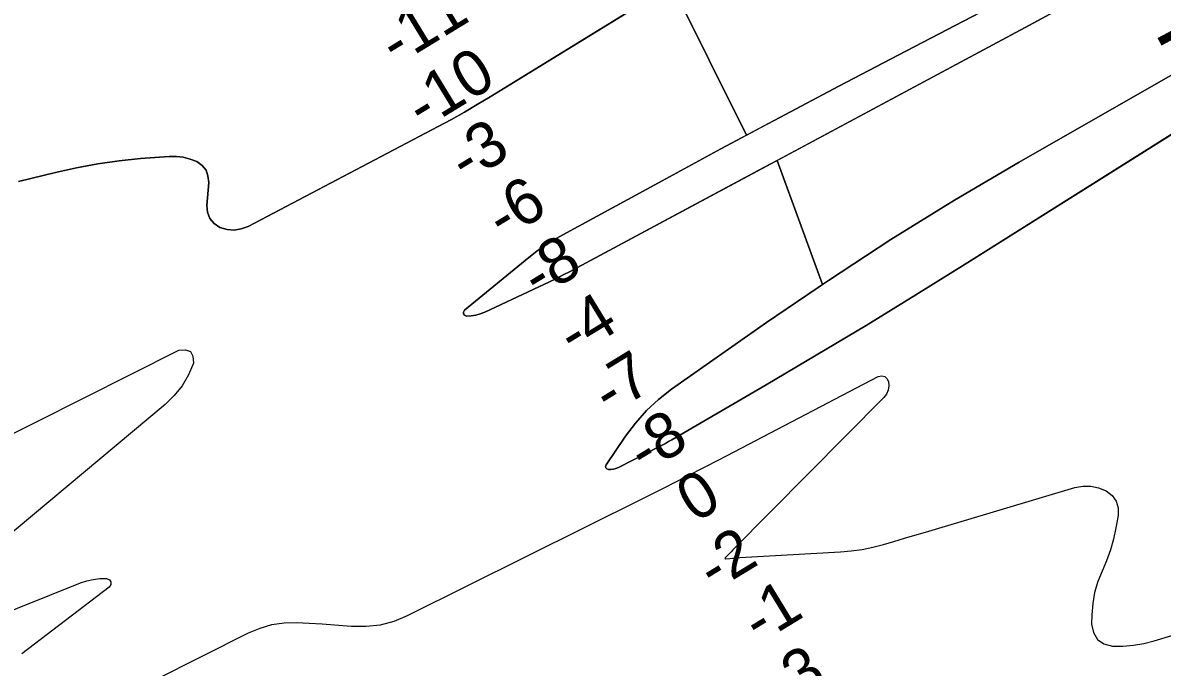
# Model space of a CAD drawing. Extents: x 3177385 to 3215275, y 903885 to 929304.
# Drawn here: x 3187679 to 3189350, y 911280 to 912224 of the extents above; entities that cross this region are included whole.
import ezdxf

# ---------------------------------------------------------------- set-up
doc = ezdxf.new("R2010")
doc.units = 0
for name, color, linetype in [('V-RIVR-RANG', 7, 'Continuous'), ('V-TOPO-DPTH', 7, 'Continuous'), ('V-TOPO-GNAM-IDEN', 7, 'Continuous'), ('V-TOPO-MINR', 7, 'Continuous')]:
    doc.layers.add(name, color=color, linetype=linetype)

msp = doc.modelspace()

# ---------------------------------------------------------------- linework, layer by layer
at = {"layer": 'V-TOPO-DPTH'}
for points in [[(3189564.8, 912490), (3189572.5, 912493.8), (3189580.2, 912497.4), (3189689.2, 912548.4), (3189695.8, 912550.8), (3189702.6, 912552.6), (3189709.6, 912553.3), (3189716.8, 912553.2), (3189719.6, 912551.5), (3189721.2, 912549.4), (3189720.7, 912546.9), (3189719, 912544.1), (3189600.1, 912467.4), (3189591.1, 912461.7), (3189582, 912456.2), (3189572.8, 912450.7), (3189563.5, 912445.4), (3189438.2, 912375.2), (3189366.1, 912335.1), (3189293.8, 912295.3), (3189221.3, 912255.9), (3189148.7, 912216.7), (3188785.3, 912022.1)], [(3189549.5, 912482.3), (3188962.3, 912176.5), (3188875.6, 912131), (3188789, 912085.2), (3188702.6, 912039), (3188616.4, 911992.5), (3188470.7, 911913.4), (3188457.7, 911905.8), (3188445.1, 911897.8), (3188432.8, 911889.1), (3188420.9, 911880), (3188326.6, 911803), (3188325.2, 911800), (3188325, 911797.4), (3188326.8, 911795.5), (3188329.8, 911794.1), (3188336.6, 911794.5), (3188343.4, 911795.5), (3188349.9, 911797.4), (3188356.4, 911799.9), (3188451.3, 911844.6), (3188461.4, 911849.4), (3188471.4, 911854.4), (3188481.4, 911859.5), (3188491.3, 911864.7), (3189148.7, 912216.7), (3189221.3, 912255.9)], [(3188651.4, 912291.8), (3188630.9, 912279.2), (3188740.2, 912059.2), (3188762.3, 912070.9), (3188789, 912085.2), (3188875.6, 912131), (3188962.3, 912176.5), (3189549.5, 912482.3), (3189557.1, 912486.2), (3189564.8, 912490)], [(3188942.4, 912470.6), (3188364.1, 912115.2), (3188345.4, 912103.9), (3188326.5, 912092.9), (3188307.4, 912082.3), (3188288.2, 912072), (3188009.6, 911925.5), (3187999.3, 911921.8), (3187988.9, 911920), (3187978.5, 911921.1), (3187968, 911924.1), (3187959.6, 911930), (3187953.2, 911937.2), (3187950, 911946.2), (3187948.8, 911956.4), (3187951.7, 911990.1), (3187950.6, 911999.6), (3187947.7, 912008), (3187941.9, 912014.9), (3187934.2, 912020.6), (3187924.4, 912024.3), (3187914.4, 912027), (3187904.2, 912028.1), (3187893.7, 912028.1), (3187851.7, 912024.8), (3187820.2, 912021.5), (3187788.9, 912017.2), (3187757.8, 912011.4), (3187726.8, 912004.6), (3187673, 911991.4)], [(3188785.3, 912022.1), (3188851.8, 911840.7), (3188860.3, 911846.5), (3188952, 911906.5), (3189045.3, 911963.9), (3189139.7, 912019.7), (3189637.3, 912304.4), (3189645.8, 912309.1), (3189654.4, 912313.8), (3189663.2, 912318.2), (3189671.9, 912322.5), (3189804.6, 912385.7), (3189813.9, 912389.4), (3189823.3, 912392.1), (3189833, 912393.6), (3189843, 912394.1), (3189847, 912392), (3189849.4, 912389.3), (3189849, 912385.8), (3189846.9, 912381.8), (3189714.5, 912284.4), (3189698, 912272.5), (3189681.2, 912260.9)], [(3189637.3, 912304.4), (3189139.7, 912019.7), (3189045.3, 911963.9), (3188952, 911906.5), (3188860.3, 911846.5), (3188769.7, 911784.8), (3188630.3, 911687), (3188611.2, 911672), (3188593.3, 911655.7), (3188577.3, 911637.5), (3188562.6, 911618.2), (3188534.2, 911576.2), (3188533.6, 911573.8), (3188533.9, 911571.8), (3188535.3, 911570.4), (3188537.6, 911569.3), (3188541.4, 911569.4), (3188545.2, 911569.9), (3188548.8, 911571), (3188552.3, 911572.4), (3188611.5, 911602.5), (3188616.4, 911605), (3188621.2, 911607.6), (3188626, 911610.3), (3188630.8, 911613), (3188768.8, 911693.4), (3188842.3, 911736.7), (3188915.5, 911780.5), (3188988.2, 911825.1), (3189060.7, 911870.1), (3189647.1, 912238.5)], [(3188740.2, 912059.2), (3188630.9, 912279.2), (3188364.1, 912115.2), (3188345.4, 912103.9), (3188326.5, 912092.9), (3188307.4, 912082.3), (3188288.2, 912072), (3188009.6, 911925.5), (3187999.3, 911921.8), (3187988.9, 911920), (3187978.5, 911921.1), (3187968, 911924.1), (3187959.6, 911930), (3187953.2, 911937.2), (3187950, 911946.2), (3187948.8, 911956.4), (3187951.7, 911990.1), (3187950.6, 911999.6), (3187947.7, 912008), (3187941.9, 912014.9), (3187934.2, 912020.6), (3187924.4, 912024.3), (3187914.4, 912027), (3187904.2, 912028.1), (3187893.7, 912028.1), (3187851.7, 912024.8), (3187820.2, 912021.5), (3187788.9, 912017.2), (3187757.8, 912011.4), (3187726.8, 912004.6), (3187673, 911991.4)], [(3189480.2, 912133.7), (3189060.7, 911870.1), (3188988.2, 911825.1), (3188915.5, 911780.5), (3188842.3, 911736.7), (3188768.8, 911693.4), (3188630.8, 911613), (3188626, 911610.3), (3188621.2, 911607.6), (3188616.4, 911605), (3188611.5, 911602.5), (3188552.3, 911572.4), (3188548.8, 911571), (3188545.2, 911569.9), (3188541.4, 911569.4), (3188537.6, 911569.3), (3188535.3, 911570.4), (3188533.9, 911571.8), (3188533.6, 911573.8), (3188534.2, 911576.2), (3188562.6, 911618.2), (3188577.3, 911637.5), (3188593.3, 911655.7), (3188611.2, 911672), (3188630.3, 911687), (3188769.7, 911784.8), (3188840.7, 911833.1)], [(3188840.7, 911833.1), (3188851.8, 911840.7), (3188785.3, 912022.1), (3188765.8, 912011.7), (3188491.3, 911864.7), (3188481.4, 911859.5), (3188471.4, 911854.4), (3188461.4, 911849.4), (3188451.3, 911844.6), (3188356.4, 911799.9), (3188349.9, 911797.4), (3188343.4, 911795.5), (3188336.6, 911794.5), (3188329.8, 911794.1), (3188326.8, 911795.5), (3188325, 911797.4), (3188325.2, 911800), (3188326.6, 911803), (3188420.9, 911880), (3188432.8, 911889.1), (3188445.1, 911897.8), (3188457.7, 911905.8), (3188470.7, 911913.4), (3188616.4, 911992.5), (3188702.6, 912039), (3188740.2, 912059.2)]]:
    msp.add_lwpolyline(points, dxfattribs=at)
at = {"layer": 'V-TOPO-MINR'}
for points in [[(3189549.5, 912482.3), (3188962.3, 912176.5), (3188875.6, 912131), (3188789, 912085.2), (3188702.6, 912039), (3188616.4, 911992.5), (3188470.7, 911913.4), (3188457.7, 911905.8), (3188445.1, 911897.8), (3188432.8, 911889.1), (3188420.9, 911880), (3188326.6, 911803), (3188325.2, 911800), (3188325, 911797.4), (3188326.8, 911795.5), (3188329.8, 911794.1), (3188336.6, 911794.5), (3188343.4, 911795.5), (3188349.9, 911797.4), (3188356.4, 911799.9), (3188451.3, 911844.6), (3188461.4, 911849.4), (3188471.4, 911854.4), (3188481.4, 911859.5), (3188491.3, 911864.7), (3189148.7, 912216.7), (3189221.3, 912255.9)], [(3187673, 911991.4), (3187726.8, 912004.6), (3187757.8, 912011.4), (3187788.9, 912017.2), (3187820.2, 912021.5), (3187851.7, 912024.8), (3187893.7, 912028.1), (3187904.2, 912028.1), (3187914.4, 912027), (3187924.4, 912024.3), (3187934.2, 912020.6), (3187941.9, 912014.9), (3187947.7, 912008), (3187950.6, 911999.6), (3187951.7, 911990.1), (3187948.8, 911956.4), (3187950, 911946.2), (3187953.2, 911937.2), (3187959.6, 911930), (3187968, 911924.1), (3187978.5, 911921.1), (3187988.9, 911920), (3187999.3, 911921.8), (3188009.6, 911925.5), (3188288.2, 912072), (3188307.4, 912082.3), (3188326.5, 912092.9), (3188345.4, 912103.9), (3188364.1, 912115.2), (3188942.4, 912470.6)], [(3189637.3, 912304.4), (3189139.7, 912019.7), (3189045.3, 911963.9), (3188952, 911906.5), (3188860.3, 911846.5), (3188769.7, 911784.8), (3188630.3, 911687), (3188611.2, 911672), (3188593.3, 911655.7), (3188577.3, 911637.5), (3188562.6, 911618.2), (3188534.2, 911576.2), (3188533.6, 911573.8), (3188533.9, 911571.8), (3188535.3, 911570.4), (3188537.6, 911569.3), (3188541.4, 911569.4), (3188545.2, 911569.9), (3188548.8, 911571), (3188552.3, 911572.4), (3188611.5, 911602.5), (3188616.4, 911605), (3188621.2, 911607.6), (3188626, 911610.3), (3188630.8, 911613), (3188768.8, 911693.4), (3188842.3, 911736.7), (3188915.5, 911780.5), (3188988.2, 911825.1), (3189060.7, 911870.1), (3189647.1, 912238.5)], [(3187488, 911533.5), (3187907.7, 911744.4), (3187917.6, 911744.8), (3187924.9, 911742.2), (3187928.5, 911735.3), (3187929.5, 911725.4), (3187922, 911708.2), (3187912.9, 911692.2), (3187901.2, 911677.9), (3187887.9, 911664.8), (3187573.3, 911402)], [(3187733.2, 911190.8), (3188010, 911330.2), (3188026.9, 911337.2), (3188044.3, 911342.3), (3188062.2, 911344.7), (3188080.5, 911345.4), (3188099.1, 911344.4), (3188117.8, 911343.3), (3188136.3, 911342), (3188154.9, 911340.4), (3188161.1, 911339.9), (3188182.4, 911339.8), (3188203.3, 911341.9), (3188223.5, 911347.5), (3188243.3, 911355.4), (3188589.9, 911528), (3188620.5, 911543.3), (3188650.9, 911558.7), (3188681.3, 911574.3), (3188711.7, 911590), (3188933.4, 911705.7), (3188938.5, 911706.5), (3188942.8, 911705.8), (3188946, 911702.9), (3188948.5, 911698.4), (3188948.8, 911691.9), (3188947.9, 911685.7), (3188945.2, 911680), (3188941.3, 911674.7), (3188720.1, 911451.6), (3188717.6, 911449), (3188715, 911446.4), (3188709.5, 911440.7), (3188709, 911440), (3188708.6, 911439.2), (3188708.7, 911438.9), (3188708.8, 911438.7), (3188709.3, 911438.5), (3188715.8, 911439.1), (3188719.4, 911439.5), (3188723.1, 911439.8), (3188726.8, 911440.1), (3188730.4, 911440.3), (3188877.8, 911448.8), (3188893.8, 911450.2), (3188909.6, 911452.4), (3188925.3, 911455.7), (3188940.8, 911459.6), (3188956.3, 911464.2), (3188971.7, 911468.7), (3188987.2, 911473.3), (3189002.6, 911477.8), (3189221.7, 911542.9), (3189233.4, 911544.9), (3189245, 911545.1), (3189256.4, 911542.6), (3189267.5, 911538.4), (3189276.1, 911531.4), (3189282.2, 911523.2), (3189284.9, 911513.3), (3189285.2, 911502.3), (3189281.9, 911483.9), (3189278.4, 911467.6), (3189273.9, 911451.6), (3189268.2, 911435.9), (3189261.6, 911420.6), (3189255.4, 911405.2), (3189250.6, 911389.5), (3189247.8, 911373.3), (3189246.4, 911356.7), (3189246.1, 911343), (3189249.1, 911330.5), (3189254.7, 911320.5), (3189264.3, 911314.3), (3189276.6, 911310.7), (3189292.1, 911310.9), (3189307.5, 911312.1), (3189322.7, 911314.8), (3189337.8, 911318.5), (3189415.4, 911341.7)], [(3187625.7, 911348.1), (3187763.6, 911403.2), (3187772.9, 911406.3), (3187782.4, 911408.5), (3187792, 911409.6), (3187801.8, 911409.8), (3187806, 911407.6), (3187808.3, 911404.8), (3187808, 911401.2), (3187805.8, 911397), (3187677.5, 911299.4)]]:
    msp.add_lwpolyline(points, dxfattribs=at)

# ---------------------------------------------------------------- texts
at = {"layer": 'V-RIVR-RANG'}
for s, p in [('-11', (3188226.5, 912160.1)), ('-10', (3188265.8, 912067)), ('-3', (3188328.8, 911988.2)), ('-6', (3188383.4, 911904.4)), ('-8', (3188434.8, 911818.7)), ('-4', (3188487.4, 911733.6)), ('-7', (3188539.1, 911648)), ('-8', (3188590.6, 911562.3)), ('0', (3188664.7, 911490.4)), ('-2', (3188692.6, 911390.2)), ('-1', (3188758.7, 911313.4)), ('3', (3188818.4, 911232.8))]:
    msp.add_text(s, height=67, rotation=31.4308, dxfattribs=at).set_placement(p)
at = {"layer": 'V-TOPO-GNAM-IDEN'}
msp.add_text('TARBERT LANDING DISCHARGE RANGE', height=100, rotation=298.2461, dxfattribs=at).set_placement((3189069.7, 912709.7))

doc.saveas('drawing.dxf')
